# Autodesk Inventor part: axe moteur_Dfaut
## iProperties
Created: 2007-07
Part Number: axe moteur_Dfaut
Document SubType Name: Modeling
Designer: EF
Density: 1 g/cm^3
Author: EF
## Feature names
1. Base1
